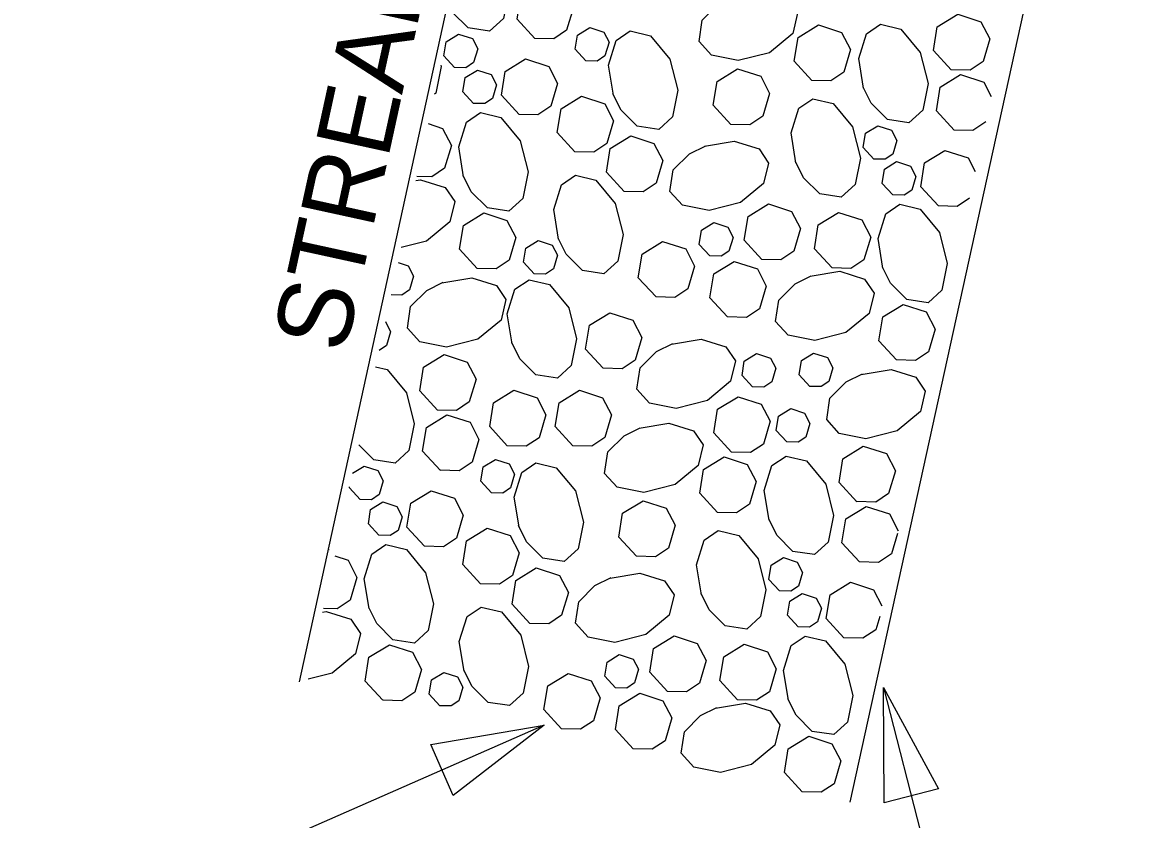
# Model space of a CAD drawing. Extents: x 2126110 to 2128246, y 1804858 to 1811658.
# Drawn here: x 2127014.3 to 2127316.2, y 1810786.4 to 1811000.5 of the extents above; entities that cross this region are included whole.
import ezdxf

# ---------------------------------------------------------------- set-up
doc = ezdxf.new("R2010")
doc.units = 0
doc.layers.add('Old_Level_1', color=7, linetype='Continuous')

msp = doc.modelspace()

# ---------------------------------------------------------------- linework, layer by layer
at = {"layer": 'Old_Level_1'}
for p, q in [((2127160.92, 1811154.64), (2127088.55, 1810823.46)), ((2127236.39, 1810791.15), (2127316.2, 1811154.76)), ((2127096.43, 1810858.85), (2127096.53, 1810859.07)), ((2127245.32, 1810821.88), (2127274.88, 1810707.22)), ((2127154.3, 1810811.78), (2127014.25, 1810750.36))]:
    msp.add_line(p, q, dxfattribs=at)
for points in [[(2127134.07, 1811024.11), (2127137.46, 1811023.3), (2127142.63, 1811017.05), (2127144.76, 1811008.68), (2127143.33, 1811001.54), (2127139.61, 1810998.15), (2127133.86, 1810999.01), (2127129.58, 1811003.29)], [(2127151.74, 1810996.2), (2127147, 1811001.36), (2127148.01, 1811007.74), (2127153.5, 1811011.12), (2127159.72, 1811009.1), (2127162.11, 1811004.5), (2127160.3, 1810998.39), (2127156.82, 1810996.09), (2127151.75, 1810996.2)], [(2127205.08, 1811007.53), (2127213.09, 1811008.84), (2127219.74, 1811006.78), (2127222.29, 1811003.01), (2127220.98, 1810997.54), (2127214.73, 1810992.36), (2127206.36, 1810990.24), (2127199.22, 1810991.67), (2127195.83, 1810995.39), (2127196.69, 1811001.14), (2127201.05, 1811005.5), (2127205.42, 1811007.65)], [(2127263.51, 1810987.79), (2127258.77, 1810992.95), (2127259.78, 1810999.32), (2127265.27, 1811002.71), (2127271.49, 1811000.69), (2127273.87, 1810996.09), (2127272.06, 1810989.98), (2127268.59, 1810987.68), (2127263.51, 1810987.79)], [(2127226.13, 1810984.91), (2127221.38, 1810990.07), (2127222.4, 1810996.44), (2127227.89, 1810999.83), (2127234.1, 1810997.8), (2127236.49, 1810993.21), (2127234.68, 1810987.1), (2127231.21, 1810984.8), (2127226.13, 1810984.91)], [(2127240, 1810982.81), (2127238.69, 1810990.82), (2127240.76, 1810997.46), (2127244.52, 1811000.01), (2127249.99, 1810998.71), (2127255.17, 1810992.46), (2127257.29, 1810984.09), (2127255.87, 1810976.95), (2127252.15, 1810973.56), (2127246.39, 1810974.42), (2127242.04, 1810978.78), (2127239.88, 1810983.15)], [(2127130.21, 1810988.4), (2127127.36, 1810991.5), (2127127.97, 1810995.32), (2127131.27, 1810997.35), (2127135, 1810996.14), (2127136.43, 1810993.38), (2127135.34, 1810989.71), (2127133.26, 1810988.33), (2127130.21, 1810988.4)], [(2127165.45, 1810990.18), (2127162.61, 1810993.28), (2127163.22, 1810997.1), (2127166.51, 1810999.13), (2127170.24, 1810997.92), (2127171.67, 1810995.17), (2127170.59, 1810991.49), (2127168.5, 1810990.11), (2127165.46, 1810990.18)], [(2127172.86, 1810981.01), (2127171.55, 1810989.02), (2127173.62, 1810995.67), (2127177.38, 1810998.21), (2127182.85, 1810996.91), (2127188.03, 1810990.66), (2127190.15, 1810982.29), (2127188.72, 1810975.15), (2127185, 1810971.76), (2127179.25, 1810972.62), (2127174.89, 1810976.98), (2127172.74, 1810981.35)], [(2127147.53, 1810975.82), (2127142.79, 1810980.98), (2127143.8, 1810987.35), (2127149.29, 1810990.74), (2127155.51, 1810988.71), (2127157.89, 1810984.12), (2127156.09, 1810978.01), (2127152.61, 1810975.7), (2127147.53, 1810975.82)], [(2127126.5, 1810989.03), (2127126.59, 1810988.68), (2127125.16, 1810981.54), (2127124.82, 1810981.23)], [(2127135.27, 1810978.77), (2127132.42, 1810981.87), (2127133.03, 1810985.69), (2127136.33, 1810987.72), (2127140.06, 1810986.51), (2127141.49, 1810983.75), (2127140.4, 1810980.09), (2127138.32, 1810978.7), (2127135.27, 1810978.77)], [(2127204.41, 1810973.13), (2127199.66, 1810978.3), (2127200.68, 1810984.67), (2127206.17, 1810988.05), (2127212.39, 1810986.03), (2127214.77, 1810981.44), (2127212.96, 1810975.32), (2127209.49, 1810973.02), (2127204.41, 1810973.13)], [(2127264.28, 1810971.61), (2127259.54, 1810976.77), (2127260.55, 1810983.14), (2127266.04, 1810986.53), (2127272.26, 1810984.5), (2127274.27, 1810980.63)], [(2127162.53, 1810965.77), (2127157.79, 1810970.93), (2127158.8, 1810977.3), (2127164.3, 1810980.69), (2127170.51, 1810978.66), (2127172.9, 1810974.07), (2127171.09, 1810967.96), (2127167.61, 1810965.65), (2127162.53, 1810965.77)], [(2127221.84, 1810962.82), (2127220.53, 1810970.82), (2127222.59, 1810977.47), (2127226.36, 1810980.02), (2127231.83, 1810978.72), (2127237, 1810972.47), (2127239.13, 1810964.09), (2127237.7, 1810956.95), (2127233.98, 1810953.57), (2127228.23, 1810954.43), (2127223.87, 1810958.78), (2127221.71, 1810963.15)], [(2127132.64, 1810959.07), (2127131.33, 1810967.08), (2127133.39, 1810973.72), (2127137.16, 1810976.27), (2127142.63, 1810974.97), (2127147.8, 1810968.72), (2127149.93, 1810960.35), (2127148.5, 1810953.2), (2127144.78, 1810949.82), (2127139.03, 1810950.68), (2127134.67, 1810955.04), (2127132.52, 1810959.41)], [(2127123.11, 1810973.32), (2127126.98, 1810972.06), (2127129.36, 1810967.47), (2127127.56, 1810961.35), (2127124.08, 1810959.05), (2127120.05, 1810959.14)], [(2127242.75, 1810963.8), (2127239.9, 1810966.9), (2127240.51, 1810970.73), (2127243.8, 1810972.76), (2127247.53, 1810971.54), (2127248.96, 1810968.79), (2127247.88, 1810965.12), (2127245.8, 1810963.74), (2127242.75, 1810963.81)], [(2127272.8, 1810973.78), (2127269.36, 1810971.49), (2127264.28, 1810971.61)], [(2127175.74, 1810955.11), (2127171, 1810960.28), (2127172.01, 1810966.65), (2127177.51, 1810970.03), (2127183.72, 1810968.01), (2127186.1, 1810963.42), (2127184.3, 1810957.3), (2127180.82, 1810955), (2127175.74, 1810955.11)], [(2127197.28, 1810967.27), (2127205.29, 1810968.58), (2127211.94, 1810966.52), (2127214.49, 1810962.75), (2127213.18, 1810957.28), (2127206.94, 1810952.11), (2127198.56, 1810949.98), (2127191.42, 1810951.41), (2127188.04, 1810955.13), (2127188.9, 1810960.88), (2127193.25, 1810965.24), (2127197.62, 1810967.39)], [(2127260.07, 1810951.22), (2127255.33, 1810956.39), (2127256.34, 1810962.76), (2127261.83, 1810966.14), (2127268.05, 1810964.12), (2127269.95, 1810960.46)], [(2127247.81, 1810954.18), (2127244.96, 1810957.28), (2127245.57, 1810961.1), (2127248.86, 1810963.13), (2127252.6, 1810961.92), (2127254.03, 1810959.16), (2127252.94, 1810955.49), (2127250.86, 1810954.11), (2127247.81, 1810954.18)], [(2127119.81, 1810958.05), (2127121.09, 1810958.26), (2127127.74, 1810956.19), (2127130.29, 1810952.43), (2127128.98, 1810946.96), (2127122.73, 1810941.78), (2127115.93, 1810940.05)], [(2127158.15, 1810942.26), (2127156.84, 1810950.27), (2127158.9, 1810956.92), (2127162.67, 1810959.47), (2127168.14, 1810958.16), (2127173.32, 1810951.91), (2127175.44, 1810943.54), (2127174.01, 1810936.4), (2127170.29, 1810933.02), (2127164.54, 1810933.87), (2127160.18, 1810938.23), (2127158.03, 1810942.6)], [(2127212.71, 1810936.85), (2127207.97, 1810942.01), (2127208.99, 1810948.38), (2127214.48, 1810951.77), (2127220.69, 1810949.74), (2127223.08, 1810945.15), (2127221.27, 1810939.04), (2127217.8, 1810936.73), (2127212.72, 1810936.85)], [(2127245.18, 1810934.48), (2127243.87, 1810942.49), (2127245.93, 1810949.13), (2127249.69, 1810951.68), (2127255.17, 1810950.38), (2127260.34, 1810944.13), (2127262.47, 1810935.75), (2127261.04, 1810928.61), (2127257.32, 1810925.23), (2127251.57, 1810926.09), (2127247.21, 1810930.44), (2127245.05, 1810934.82)], [(2127268.41, 1810953.27), (2127265.15, 1810951.11), (2127260.07, 1810951.23)], [(2127136.31, 1810934.45), (2127131.57, 1810939.62), (2127132.59, 1810945.99), (2127138.08, 1810949.37), (2127144.29, 1810947.35), (2127146.68, 1810942.76), (2127144.87, 1810936.64), (2127141.4, 1810934.34), (2127136.32, 1810934.46)], [(2127231.54, 1810934.57), (2127226.8, 1810939.74), (2127227.81, 1810946.11), (2127233.3, 1810949.49), (2127239.52, 1810947.47), (2127241.9, 1810942.87), (2127240.1, 1810936.76), (2127236.62, 1810934.46), (2127231.54, 1810934.57)], [(2127198.73, 1810937.8), (2127195.88, 1810940.9), (2127196.49, 1810944.72), (2127199.79, 1810946.75), (2127203.52, 1810945.54), (2127204.95, 1810942.78), (2127203.86, 1810939.11), (2127201.78, 1810937.73), (2127198.73, 1810937.8)], [(2127151.6, 1810932.99), (2127148.75, 1810936.1), (2127149.37, 1810939.92), (2127152.66, 1810941.95), (2127156.39, 1810940.73), (2127157.82, 1810937.98), (2127156.73, 1810934.31), (2127154.65, 1810932.93), (2127151.6, 1810933)], [(2127184.29, 1810926.77), (2127179.54, 1810931.93), (2127180.56, 1810938.3), (2127186.05, 1810941.69), (2127192.26, 1810939.67), (2127194.65, 1810935.07), (2127192.84, 1810928.96), (2127189.37, 1810926.66), (2127184.29, 1810926.77)], [(2127203.51, 1810921.41), (2127198.77, 1810926.58), (2127199.78, 1810932.95), (2127205.27, 1810936.33), (2127211.49, 1810934.31), (2127213.87, 1810929.71), (2127212.06, 1810923.6), (2127208.59, 1810921.3), (2127203.51, 1810921.41)], [(2127115.05, 1810935.99), (2127117.79, 1810935.1), (2127119.22, 1810932.35), (2127118.13, 1810928.68), (2127116.05, 1810927.29), (2127113.19, 1810927.36)], [(2127225.62, 1810932.35), (2127233.63, 1810933.67), (2127240.28, 1810931.6), (2127242.83, 1810927.84), (2127241.52, 1810922.36), (2127235.27, 1810917.19), (2127226.9, 1810915.06), (2127219.76, 1810916.49), (2127216.38, 1810920.21), (2127217.23, 1810925.96), (2127221.59, 1810930.32), (2127225.96, 1810932.48)], [(2127126.81, 1810930.58), (2127134.82, 1810931.9), (2127141.46, 1810929.83), (2127144.01, 1810926.07), (2127142.71, 1810920.59), (2127136.46, 1810915.42), (2127128.08, 1810913.29), (2127120.94, 1810914.72), (2127117.56, 1810918.44), (2127118.42, 1810924.19), (2127122.77, 1810928.55), (2127127.14, 1810930.71)], [(2127145.68, 1810914.21), (2127144.37, 1810922.23), (2127146.43, 1810928.87), (2127150.2, 1810931.42), (2127155.67, 1810930.12), (2127160.85, 1810923.87), (2127162.97, 1810915.49), (2127161.54, 1810908.35), (2127157.82, 1810904.97), (2127152.07, 1810905.83), (2127147.71, 1810910.18), (2127145.56, 1810914.56)], [(2127248.85, 1810909.86), (2127244.11, 1810915.03), (2127245.13, 1810921.4), (2127250.62, 1810924.78), (2127256.83, 1810922.76), (2127259.21, 1810918.17), (2127257.41, 1810912.05), (2127253.94, 1810909.75), (2127248.85, 1810909.87)], [(2127170.12, 1810907.63), (2127165.37, 1810912.79), (2127166.39, 1810919.16), (2127171.88, 1810922.55), (2127178.09, 1810920.52), (2127180.48, 1810915.93), (2127178.67, 1810909.82), (2127175.2, 1810907.52), (2127170.12, 1810907.63)], [(2127111.64, 1810920.16), (2127113.05, 1810917.43), (2127111.97, 1810913.76), (2127109.97, 1810912.43)], [(2127188.42, 1810914.13), (2127196.43, 1810915.44), (2127203.07, 1810913.37), (2127205.62, 1810909.61), (2127204.32, 1810904.14), (2127198.07, 1810898.96), (2127189.7, 1810896.84), (2127182.55, 1810898.27), (2127179.17, 1810901.99), (2127180.03, 1810907.73), (2127184.39, 1810912.1), (2127188.76, 1810914.25)], [(2127125.63, 1810896.39), (2127120.88, 1810901.56), (2127121.9, 1810907.93), (2127127.39, 1810911.31), (2127133.61, 1810909.29), (2127135.99, 1810904.7), (2127134.18, 1810898.59), (2127130.71, 1810896.28), (2127125.63, 1810896.4)], [(2127210.21, 1810902.63), (2127207.37, 1810905.73), (2127207.98, 1810909.56), (2127211.27, 1810911.58), (2127215, 1810910.37), (2127216.43, 1810907.62), (2127215.35, 1810903.95), (2127213.26, 1810902.56), (2127210.22, 1810902.63)], [(2127225.54, 1810902.77), (2127222.69, 1810905.87), (2127223.3, 1810909.69), (2127226.6, 1810911.72), (2127230.32, 1810910.51), (2127231.76, 1810907.75), (2127230.67, 1810904.08), (2127228.59, 1810902.7), (2127225.54, 1810902.77)], [(2127109.02, 1810908.05), (2127112.11, 1810907.32), (2127117.29, 1810901.07), (2127119.41, 1810892.69), (2127117.98, 1810885.55), (2127114.26, 1810882.17), (2127108.51, 1810883.03), (2127104.49, 1810887.05)], [(2127239.35, 1810905.99), (2127247.36, 1810907.31), (2127254, 1810905.24), (2127256.55, 1810901.48), (2127255.25, 1810896), (2127249, 1810890.82), (2127240.62, 1810888.7), (2127233.48, 1810890.13), (2127230.1, 1810893.85), (2127230.96, 1810899.6), (2127235.31, 1810903.96), (2127239.68, 1810906.12)], [(2127144.38, 1810886.79), (2127139.64, 1810891.96), (2127140.66, 1810898.33), (2127146.14, 1810901.71), (2127152.36, 1810899.69), (2127154.74, 1810895.1), (2127152.94, 1810888.98), (2127149.47, 1810886.68), (2127144.38, 1810886.8)], [(2127161.98, 1810886.83), (2127157.23, 1810892), (2127158.25, 1810898.37), (2127163.74, 1810901.75), (2127169.95, 1810899.73), (2127172.34, 1810895.14), (2127170.53, 1810889.02), (2127167.06, 1810886.72), (2127161.98, 1810886.84)], [(2127204.57, 1810885.08), (2127199.82, 1810890.25), (2127200.83, 1810896.62), (2127206.33, 1810900), (2127212.54, 1810897.98), (2127214.93, 1810893.38), (2127213.12, 1810887.27), (2127209.64, 1810884.97), (2127204.57, 1810885.08)], [(2127126.4, 1810880.21), (2127121.65, 1810885.38), (2127122.67, 1810891.75), (2127128.16, 1810895.13), (2127134.38, 1810893.11), (2127136.76, 1810888.52), (2127134.95, 1810882.4), (2127131.48, 1810880.1), (2127126.4, 1810880.22)], [(2127219.38, 1810887.85), (2127216.53, 1810890.95), (2127217.14, 1810894.77), (2127220.43, 1810896.8), (2127224.16, 1810895.59), (2127225.59, 1810892.83), (2127224.51, 1810889.17), (2127222.42, 1810887.78), (2127219.38, 1810887.85)], [(2127179.74, 1810891.54), (2127187.75, 1810892.86), (2127194.39, 1810890.79), (2127196.94, 1810887.03), (2127195.64, 1810881.55), (2127189.39, 1810876.38), (2127181.01, 1810874.25), (2127173.87, 1810875.68), (2127170.49, 1810879.4), (2127171.35, 1810885.15), (2127175.7, 1810889.51), (2127180.07, 1810891.67)], [(2127238.17, 1810871.8), (2127233.42, 1810876.97), (2127234.44, 1810883.34), (2127239.93, 1810886.72), (2127246.14, 1810884.7), (2127248.53, 1810880.11), (2127246.72, 1810873.99), (2127243.25, 1810871.69), (2127238.17, 1810871.81)], [(2127140.11, 1810874.2), (2127137.26, 1810877.29), (2127137.87, 1810881.12), (2127141.17, 1810883.15), (2127144.89, 1810881.93), (2127146.33, 1810879.18), (2127145.24, 1810875.51), (2127143.16, 1810874.13), (2127140.11, 1810874.2)], [(2127147.52, 1810865.03), (2127146.2, 1810873.03), (2127148.27, 1810879.68), (2127152.03, 1810882.23), (2127157.51, 1810880.93), (2127162.68, 1810874.68), (2127164.81, 1810866.3), (2127163.38, 1810859.16), (2127159.66, 1810855.78), (2127153.91, 1810856.64), (2127149.55, 1810860.99), (2127147.39, 1810865.37)], [(2127200.78, 1810868.92), (2127196.04, 1810874.09), (2127197.05, 1810880.46), (2127202.54, 1810883.84), (2127208.76, 1810881.82), (2127211.14, 1810877.23), (2127209.34, 1810871.11), (2127205.87, 1810868.81), (2127200.79, 1810868.93)], [(2127214.66, 1810866.82), (2127213.35, 1810874.83), (2127215.41, 1810881.48), (2127219.18, 1810884.03), (2127224.65, 1810882.73), (2127229.83, 1810876.48), (2127231.95, 1810868.1), (2127230.52, 1810860.96), (2127226.8, 1810857.58), (2127221.05, 1810858.44), (2127216.69, 1810862.79), (2127214.54, 1810867.16)], [(2127102.86, 1810879.47), (2127105.92, 1810881.36), (2127109.65, 1810880.15), (2127111.08, 1810877.39), (2127110, 1810873.72), (2127107.91, 1810872.34), (2127104.86, 1810872.41)], [(2127104.86, 1810872.41), (2127102.02, 1810875.51), (2127102.06, 1810875.77)], [(2127122.19, 1810859.83), (2127117.44, 1810865), (2127118.46, 1810871.37), (2127123.95, 1810874.75), (2127130.17, 1810872.73), (2127132.55, 1810868.14), (2127130.74, 1810862.02), (2127127.27, 1810859.72), (2127122.19, 1810859.84)], [(2127109.93, 1810862.79), (2127107.08, 1810865.89), (2127107.69, 1810869.71), (2127110.98, 1810871.74), (2127114.71, 1810870.53), (2127116.14, 1810867.77), (2127115.06, 1810864.1), (2127112.97, 1810862.72), (2127109.93, 1810862.79)], [(2127179.06, 1810857.15), (2127174.32, 1810862.31), (2127175.33, 1810868.68), (2127180.82, 1810872.07), (2127187.04, 1810870.04), (2127189.42, 1810865.45), (2127187.62, 1810859.34), (2127184.15, 1810857.03), (2127179.06, 1810857.15)], [(2127238.94, 1810855.62), (2127234.19, 1810860.79), (2127235.21, 1810867.16), (2127240.7, 1810870.54), (2127246.92, 1810868.52), (2127249.26, 1810864)], [(2127137.19, 1810849.78), (2127132.44, 1810854.95), (2127133.46, 1810861.32), (2127138.95, 1810864.7), (2127145.17, 1810862.68), (2127147.55, 1810858.09), (2127145.74, 1810851.97), (2127142.27, 1810849.67), (2127137.19, 1810849.78)], [(2127196.49, 1810846.83), (2127195.18, 1810854.84), (2127197.25, 1810861.48), (2127201.01, 1810864.03), (2127206.48, 1810862.73), (2127211.66, 1810856.48), (2127213.78, 1810848.11), (2127212.36, 1810840.97), (2127208.63, 1810837.58), (2127202.88, 1810838.44), (2127198.53, 1810842.8), (2127196.37, 1810847.17)], [(2127249.11, 1810863.29), (2127247.49, 1810857.81), (2127244.02, 1810855.51), (2127238.94, 1810855.63)], [(2127107.29, 1810843.08), (2127105.98, 1810851.09), (2127108.05, 1810857.74), (2127111.81, 1810860.29), (2127117.28, 1810858.98), (2127122.46, 1810852.73), (2127124.58, 1810844.36), (2127123.16, 1810837.22), (2127119.43, 1810833.84), (2127113.68, 1810834.69), (2127109.33, 1810839.05), (2127107.17, 1810843.42)], [(2127098.06, 1810857.24), (2127101.63, 1810856.07), (2127104.02, 1810851.48), (2127102.21, 1810845.37), (2127098.74, 1810843.06), (2127095.02, 1810843.15)], [(2127217.4, 1810847.82), (2127214.55, 1810850.92), (2127215.17, 1810854.74), (2127218.46, 1810856.77), (2127222.19, 1810855.56), (2127223.62, 1810852.8), (2127222.54, 1810849.13), (2127220.45, 1810847.75), (2127217.4, 1810847.82)], [(2127150.4, 1810839.13), (2127145.65, 1810844.29), (2127146.67, 1810850.66), (2127152.16, 1810854.05), (2127158.38, 1810852.02), (2127160.76, 1810847.43), (2127158.95, 1810841.32), (2127155.48, 1810839.01), (2127150.4, 1810839.13)], [(2127171.94, 1810851.28), (2127179.95, 1810852.6), (2127186.59, 1810850.53), (2127189.15, 1810846.77), (2127187.84, 1810841.3), (2127181.59, 1810836.12), (2127173.22, 1810833.99), (2127166.07, 1810835.42), (2127162.69, 1810839.14), (2127163.55, 1810844.9), (2127167.91, 1810849.25), (2127172.28, 1810851.41)], [(2127234.72, 1810835.24), (2127229.98, 1810840.41), (2127231, 1810846.78), (2127236.49, 1810850.16), (2127242.7, 1810848.14), (2127244.94, 1810843.83)], [(2127222.46, 1810838.19), (2127219.62, 1810841.3), (2127220.23, 1810845.12), (2127223.52, 1810847.15), (2127227.25, 1810845.93), (2127228.68, 1810843.18), (2127227.6, 1810839.51), (2127225.51, 1810838.13), (2127222.46, 1810838.2)], [(2127132.81, 1810826.28), (2127131.49, 1810834.29), (2127133.56, 1810840.93), (2127137.32, 1810843.48), (2127142.79, 1810842.18), (2127147.97, 1810835.93), (2127150.1, 1810827.56), (2127148.67, 1810820.41), (2127144.94, 1810817.03), (2127139.2, 1810817.89), (2127134.84, 1810822.25), (2127132.68, 1810826.62)], [(2127094.79, 1810842.12), (2127095.75, 1810842.27), (2127102.39, 1810840.21), (2127104.94, 1810836.44), (2127103.64, 1810830.97), (2127097.39, 1810825.79), (2127090.92, 1810824.15)], [(2127244.32, 1810840.95), (2127243.28, 1810837.43), (2127239.81, 1810835.13), (2127234.73, 1810835.24)], [(2127187.37, 1810820.86), (2127182.63, 1810826.03), (2127183.64, 1810832.4), (2127189.13, 1810835.78), (2127195.35, 1810833.76), (2127197.73, 1810829.17), (2127195.92, 1810823.05), (2127192.45, 1810820.75), (2127187.37, 1810820.86)], [(2127219.83, 1810818.49), (2127218.52, 1810826.5), (2127220.59, 1810833.14), (2127224.35, 1810835.69), (2127229.82, 1810834.39), (2127235, 1810828.14), (2127237.12, 1810819.77), (2127235.69, 1810812.63), (2127231.97, 1810809.24), (2127226.22, 1810810.1), (2127221.86, 1810814.46), (2127219.71, 1810818.83)], [(2127110.94, 1810818.5), (2127106.22, 1810823.63), (2127107.24, 1810830.01), (2127112.73, 1810833.39), (2127118.95, 1810831.37), (2127121.33, 1810826.77), (2127119.52, 1810820.66), (2127116.05, 1810818.35), (2127111.06, 1810818.47)], [(2127173.39, 1810821.81), (2127170.54, 1810824.91), (2127171.15, 1810828.74), (2127174.44, 1810830.76), (2127178.17, 1810829.55), (2127179.6, 1810826.8), (2127178.52, 1810823.13), (2127176.43, 1810821.75), (2127173.39, 1810821.82)], [(2127206.2, 1810818.58), (2127201.45, 1810823.75), (2127202.47, 1810830.12), (2127207.96, 1810833.5), (2127214.17, 1810831.48), (2127216.56, 1810826.89), (2127214.75, 1810820.77), (2127211.28, 1810818.47), (2127206.2, 1810818.59)], [(2127126.26, 1810817.01), (2127123.41, 1810820.11), (2127124.02, 1810823.93), (2127127.31, 1810825.96), (2127131.04, 1810824.75), (2127132.47, 1810821.99), (2127131.39, 1810818.32), (2127129.3, 1810816.94), (2127126.26, 1810817.01)], [(2127158.94, 1810810.78), (2127154.2, 1810815.95), (2127155.21, 1810822.32), (2127160.7, 1810825.7), (2127166.92, 1810823.68), (2127169.3, 1810819.09), (2127167.5, 1810812.97), (2127164.02, 1810810.67), (2127158.94, 1810810.79)], [(2127178.17, 1810805.43), (2127173.42, 1810810.59), (2127174.44, 1810816.96), (2127179.93, 1810820.34), (2127186.14, 1810818.32), (2127188.53, 1810813.73), (2127186.72, 1810807.61), (2127183.25, 1810805.31), (2127178.17, 1810805.43)], [(2127200.28, 1810816.37), (2127208.29, 1810817.68), (2127214.93, 1810815.61), (2127217.48, 1810811.85), (2127216.18, 1810806.38), (2127209.93, 1810801.2), (2127201.56, 1810799.08), (2127194.41, 1810800.51), (2127191.03, 1810804.23), (2127191.89, 1810809.98), (2127196.25, 1810814.34), (2127200.62, 1810816.49)], [(2127223.51, 1810793.88), (2127218.76, 1810799.04), (2127219.78, 1810805.41), (2127225.27, 1810808.8), (2127231.49, 1810806.77), (2127233.87, 1810802.18), (2127232.06, 1810796.07), (2127228.59, 1810793.76), (2127223.51, 1810793.88)]]:
    msp.add_lwpolyline(points, dxfattribs=at)
for points in [[(2127245.55, 1810790.96), (2127245.32, 1810821.88), (2127260.07, 1810794.7)], [(2127123.82, 1810806.6), (2127154.3, 1810811.78), (2127129.84, 1810792.86)]]:
    msp.add_lwpolyline(points, close=True, dxfattribs=at)

# ---------------------------------------------------------------- texts
msp.add_text('STREAMBED', height=20, rotation=77.6736, dxfattribs=at).set_placement((2127100.87, 1810911.23))

doc.saveas('drawing.dxf')
